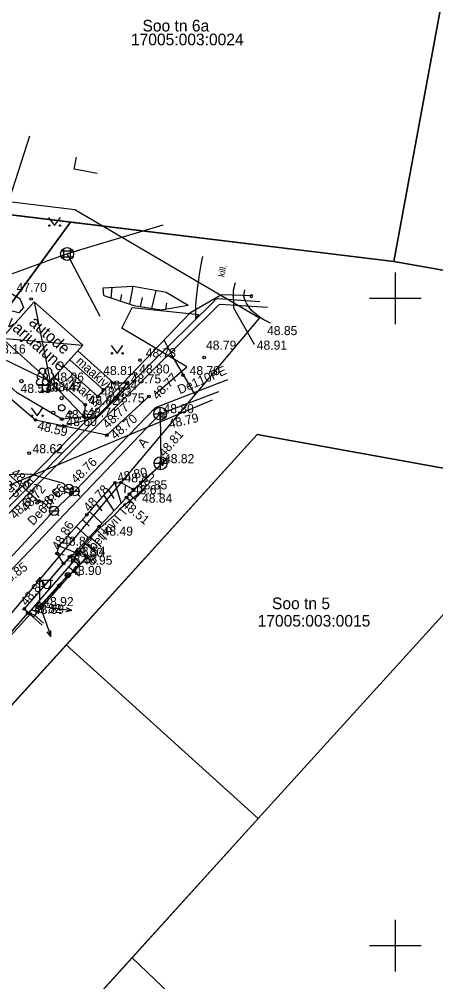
# Model space of a CAD drawing. Extents: x 640876 to 641418, y 6455595 to 6456085.
# Drawn here: x 641221 to 641253.1, y 6455847.2 to 6455921.6 of the extents above; entities that cross this region are included whole.
import ezdxf

# ---------------------------------------------------------------- set-up
doc = ezdxf.new("R2010")
doc.units = 0
for name, color, linetype in [('AED', 7, 'Continuous'), ('DKAEV', 7, 'Continuous'), ('DTRASS', 7, 'Continuous'), ('HALJASTUS', 7, 'Continuous'), ('HOONE', 7, 'Continuous'), ('HOONEDET', 7, 'Continuous'), ('KKAEV', 7, 'Continuous'), ('KORGUS', 7, 'Continuous'), ('KTRASS', 7, 'Continuous'), ('MOOTKORG', 7, 'Continuous'), ('MOOTMPUNKT', 7, 'Continuous'), ('MOOTPIIR', 7, 'Continuous'), ('MPOHULIIN', 7, 'Continuous'), ('PIIR', 7, 'Continuous'), ('POST', 7, 'Continuous'), ('PUU', 7, 'Continuous'), ('RELJEEF', 7, 'Continuous'), ('SITRASS', 7, 'Continuous'), ('TEE', 7, 'Continuous'), ('TTRASS', 7, 'Continuous'), ('VEEKOGU', 7, 'Continuous'), ('VKAEV', 7, 'Continuous'), ('VORK', 7, 'Continuous'), ('VTRASS', 7, 'Continuous')]:
    doc.layers.add(name, color=color, linetype=linetype)

msp = doc.modelspace()

# ---------------------------------------------------------------- linework, layer by layer
at = {"layer": 'AED'}
for points in [[(641221.756, 6455912.51), (641220.217, 6455907.717)], [(641221.825, 6455875.625), (641216.829, 6455870.111), (641212.099, 6455864.686)], [(641222.731, 6455874.755), (641221.819, 6455875.569)]]:
    msp.add_lwpolyline(points, dxfattribs=at)
at = {"layer": 'DKAEV'}
for p, q in [((641224.411, 6455902.987), (641224.411, 6455903.853)), ((641224.911, 6455903.853), (641224.911, 6455902.987)), ((641224.228, 6455903.67), (641225.094, 6455903.67)), ((641225.094, 6455903.17), (641224.228, 6455903.17))]:
    msp.add_line(p, q, dxfattribs=at)
msp.add_circle((641224.661, 6455903.42), 0.5, dxfattribs=at)
at = {"layer": 'DTRASS'}
for p, q in [((641232.042, 6455905.657), (641224.661, 6455903.42)), ((641224.661, 6455903.42), (641211.718, 6455898.734)), ((641225.567, 6455903.694), (641224.661, 6455903.42)), ((641227.214, 6455898.595), (641224.661, 6455903.42)), ((641220.013, 6455885.484), (641235.878, 6455892.151))]:
    msp.add_line(p, q, dxfattribs=at)
at = {"layer": 'HALJASTUS'}
for p, q in [((641223.235, 6455906.226), (641223.699, 6455905.619)), ((641223.699, 6455905.619), (641224.144, 6455906.226)), ((641228.057, 6455896.352), (641228.52, 6455895.745)), ((641228.52, 6455895.745), (641228.966, 6455896.352)), ((641221.883, 6455891.532), (641222.347, 6455890.925)), ((641222.347, 6455890.925), (641222.792, 6455891.532)), ((641221.71, 6455875.698), (641225.203, 6455879.729))]:
    msp.add_line(p, q, dxfattribs=at)
for points in [[(641225.967, 6455890.838), (641224.248, 6455890.658), (641220.812, 6455892.688), (641218.042, 6455895.173), (641218.862, 6455895.734), (641223.364, 6455893.565), (641225.967, 6455890.838)], [(641232.499, 6455887.68), (641229.484, 6455884.866), (641230.002, 6455884.376)], [(641229.917, 6455884.535), (641230.717, 6455885.322)], [(641221.355, 6455876.005), (641222.066, 6455875.392), (641225.559, 6455879.422), (641224.848, 6455880.035), (641221.355, 6455876.005)]]:
    msp.add_lwpolyline(points, dxfattribs=at)
for centre in [(641223.298, 6455905.619), (641224.126, 6455905.619), (641228.119, 6455895.745), (641228.948, 6455895.745), (641221.946, 6455890.925), (641222.775, 6455890.925)]:
    msp.add_circle(centre, 0.055, dxfattribs=at)
at = {"layer": 'HOONE'}
msp.add_lwpolyline([(641226.979, 6455909.64), (641225.211, 6455909.978), (641225.386, 6455910.893)], dxfattribs=at)
msp.add_lwpolyline([(641222.131, 6455899.722), (641219.619, 6455896.91), (641223.364, 6455893.565), (641225.876, 6455896.377)], close=True, dxfattribs=at)
at = {"layer": 'HOONEDET'}
for p, q in [((641222.131, 6455899.722), (641223.364, 6455893.565)), ((641219.619, 6455896.91), (641225.876, 6455896.377))]:
    msp.add_line(p, q, dxfattribs=at)
at = {"layer": 'KKAEV'}
for p, q in [((641231.848, 6455890.586), (641231.848, 6455891.586)), ((641231.348, 6455891.086), (641232.348, 6455891.086)), ((641231.88, 6455886.759), (641231.88, 6455887.759)), ((641231.38, 6455887.259), (641232.38, 6455887.259))]:
    msp.add_line(p, q, dxfattribs=at)
for centre in [(641231.848, 6455891.086), (641231.88, 6455887.259)]:
    msp.add_circle(centre, 0.5, dxfattribs=at)
at = {"layer": 'KORGUS'}
msp.add_line((641238.968, 6455900.207), (641238.905, 6455900.257), dxfattribs=at)
for centre in [(641221.885, 6455899.942), (641230.29, 6455895.22), (641235.25, 6455895.43), (641229.95, 6455894.17), (641233.609, 6455894.064), (641228.274, 6455893.451), (641230.967, 6455892.412), (641222.234, 6455890.597), (641226.877, 6455890.799), (641232.071, 6455890.846), (641227.727, 6455889.418), (641221.737, 6455888.032), (641231.997, 6455887.499), (641228.359, 6455885.741), (641224.942, 6455884.851), (641229.252, 6455884.61), (641222.347, 6455884.191), (641222.487, 6455884.336), (641222.525, 6455884.321), (641226.183, 6455883.28), (641227.141, 6455882.364), (641223.897, 6455880.282), (641225.559, 6455879.422), (641221.355, 6455876.005)]:
    msp.add_circle(centre, 0.1, dxfattribs=at)
msp.add_arc((641238.88, 6455900.16), 0.1, 75.27044, 28.34425, dxfattribs=at)
at = {"layer": 'KTRASS'}
for q in [(641232.097, 6455887.148), (641232.072, 6455887.115)]:
    msp.add_line((641231.88, 6455887.259), q, dxfattribs=at)
for points in [[(641231.848, 6455891.086), (641236.371, 6455892.804)], [(641216.001, 6455874.47), (641231.848, 6455891.086), (641231.899, 6455887.222)], [(641231.899, 6455887.222), (641232.051, 6455887.087)]]:
    msp.add_lwpolyline(points, dxfattribs=at)
at = {"layer": 'MOOTMPUNKT'}
for centre in [(641223.364, 6455893.565), (641229.32, 6455893.432), (641222.751, 6455892.791), (641223.215, 6455892.821), (641227.462, 6455892.937), (641227.031, 6455892.414), (641228.036, 6455891.957), (641226.069, 6455891.769), (641231.84, 6455891.123), (641224.248, 6455890.658), (641225.967, 6455890.838), (641224.354, 6455890.139), (641231.88, 6455887.259), (641228.828, 6455885.781), (641229.791, 6455885.236), (641229.484, 6455884.866), (641224.02, 6455880.889), (641224.848, 6455880.035), (641225.015, 6455880.11), (641224.378, 6455879.517), (641224.713, 6455878.622), (641222.563, 6455876.22), (641221.631, 6455875.683), (641221.825, 6455875.625)]:
    msp.add_circle(centre, 0.1, dxfattribs=at)
at = {"layer": 'MOOTPIIR'}
msp.add_lwpolyline([(641060.916, 6455895.936), (641100.061, 6455950.482), (641099.586, 6455952.159), (641069.132, 6455984.035), (641066.132, 6455988.623), (641076.463, 6456005.049), (641230.642, 6456010.048), (641237.36, 6455995.24), (641237.24, 6455992.81), (641236.258, 6455990.888), (641229.041, 6455971.315), (641203.026, 6455909.57), (641225.257, 6455906.847), (641239.512, 6455898.491), (641200.195, 6455851.697), (641192.016, 6455859.099), (641169.785, 6455829.138), (641192.025, 6455807.568), (641252.96, 6455758.075), (641231.388, 6455736.74), (641191.474, 6455775.975), (641152.419, 6455787.914), (641136.351, 6455788.307), (641049.066, 6455856.043)], dxfattribs=at)
at = {"layer": 'MPOHULIIN'}
for p, q in [((641222.735, 6455876.402), (641224.282, 6455878.035)), ((641224.282, 6455878.035), (641223.863, 6455877.811)), ((641224.282, 6455878.035), (641224.08, 6455877.605)), ((641222.563, 6455876.22), (641222.563, 6455876.22)), ((641222.563, 6455876.22), (641222.563, 6455876.22)), ((641222.563, 6455876.22), (641222.563, 6455876.22)), ((641222.648, 6455875.985), (641223.412, 6455873.869)), ((641222.811, 6455876.186), (641225.04, 6455875.878)), ((641225.04, 6455875.878), (641224.572, 6455875.793)), ((641225.04, 6455875.878), (641224.613, 6455876.089)), ((641223.412, 6455873.869), (641223.119, 6455874.243)), ((641223.412, 6455873.869), (641223.4, 6455874.344))]:
    msp.add_line(p, q, dxfattribs=at)
at = {"layer": 'PIIR'}
for points in [[(641222.58, 6455998.61), (641237.36, 6455995.24), (641235.34, 6455991.29), (641228.11, 6455971.68), (641220.5, 6455953.19), (641213.41, 6455936.25), (641201.58, 6455908.74), (641224.93, 6455905.88), (641191.87, 6455860.58), (641157.02, 6455885.66), (641160.91, 6455891.99), (641102.26, 6455951.82), (641074.95, 6455979.64), (641084.84, 6455991.92)], [(641270.69, 6455899.15), (641249.88, 6455902.84), (641253.51, 6455922.51), (641213.41, 6455936.25), (641220.5, 6455953.19), (641280.77, 6455915.37)], [(641201.58, 6455908.74), (641213.41, 6455936.25), (641253.51, 6455922.51), (641249.88, 6455902.84)], [(641239.33, 6455889.47), (641262.53, 6455885.29), (641239.42, 6455859.81), (641224.6, 6455873.24)], [(641270.46, 6455810.04), (641229.68, 6455849.06), (641239.42, 6455859.81), (641262.53, 6455885.29), (641292.55, 6455879.89), (641315.35, 6455858.84)], [(641224.6, 6455873.24), (641239.42, 6455859.81), (641199.12, 6455815.36), (641184.3, 6455828.79)], [(641250.06, 6455787.79), (641207.91, 6455825.07), (641229.68, 6455849.06), (641270.46, 6455810.04)]]:
    msp.add_lwpolyline(points, close=True, dxfattribs=at)
msp.add_lwpolyline([(641315.35, 6455858.84), (641292.55, 6455879.89), (641262.53, 6455885.29), (641239.33, 6455889.47), (641203.18, 6455849.61), (641191.84, 6455860.59), (641224.93, 6455905.88), (641249.88, 6455902.84), (641270.69, 6455899.15), (641280.77, 6455915.37), (641291.33, 6455932.26), (641301.94, 6455948.72)], dxfattribs=at)
at = {"layer": 'POST'}
for p, q in [((641224.713, 6455878.622), (641222.563, 6455876.22)), ((641222.563, 6455876.47), (641222.563, 6455878.47)), ((641222.563, 6455878.22), (641223.563, 6455878.22)), ((641222.79, 6455877.899), (641222.79, 6455878.22)), ((641223.402, 6455877.899), (641223.402, 6455878.22)), ((641222.563, 6455876.22), (641222.563, 6455876.22))]:
    msp.add_line(p, q, dxfattribs=at)
for centre, radius in [((641224.713, 6455878.622), 0.2), ((641222.563, 6455876.22), 0.25)]:
    msp.add_circle(centre, radius, dxfattribs=at)
msp.add_arc((641223.096, 6455877.899), 0.306, 180, 0, dxfattribs=at)
at = {"layer": 'PUU'}
for p, q in [((641222.991, 6455893.266), (641222.511, 6455893.266)), ((641222.751, 6455892.791), (641222.751, 6455893.266)), ((641223.131, 6455892.791), (641222.751, 6455892.791)), ((641223.455, 6455893.296), (641222.975, 6455893.296)), ((641223.215, 6455892.821), (641223.215, 6455893.296)), ((641223.595, 6455892.821), (641223.215, 6455892.821))]:
    msp.add_line(p, q, dxfattribs=at)
for centre, radius in [((641221.133, 6455893.601), 0.125), ((641224.244, 6455892.287), 0.125), ((641223.594, 6455891.162), 0.125), ((641224.244, 6455891.537), 0.25), ((641224.894, 6455891.162), 0.125)]:
    msp.add_circle(centre, radius, dxfattribs=at)
for centre, radius, start, end in [((641222.581, 6455893.964), 0.233, 109.02174, 253.14154), ((641222.751, 6455894.311), 0.277, 332.5799, 207.4201), ((641223.045, 6455893.994), 0.233, 109.02174, 253.14154), ((641223.215, 6455894.341), 0.277, 332.5799, 207.4201), ((641222.921, 6455893.964), 0.233, 286.85082, 70.98591), ((641223.385, 6455893.994), 0.233, 286.85082, 70.98591), ((641222.514, 6455893.503), 0.238, 90.0016, 269.3953), ((641222.978, 6455893.533), 0.238, 90.0016, 269.3953), ((641222.988, 6455893.503), 0.238, 270.6047, 89.9984), ((641223.452, 6455893.533), 0.238, 270.6047, 89.9984)]:
    msp.add_arc(centre, radius, start, end, dxfattribs=at)
at = {"layer": 'RELJEEF'}
for p, q in [((641228.359, 6455885.741), (641228.827, 6455884.158)), ((641229.154, 6455885.597), (641229.113, 6455884.977)), ((641227.508, 6455884.778), (641228.279, 6455883.575)), ((641227.87, 6455885.188), (641228.269, 6455884.539)), ((641226.917, 6455884.11), (641227.353, 6455883.58)), ((641226.395, 6455883.52), (641227.375, 6455882.613)), ((641225.362, 6455882.372), (641226.326, 6455881.5)), ((641225.841, 6455882.902), (641226.363, 6455882.406)), ((641224.691, 6455881.631), (641225.254, 6455881.327)), ((641224.02, 6455880.889), (641225.268, 6455880.379)), ((641223.897, 6455880.282), (641224.434, 6455880.173)), ((641224.378, 6455879.517), (641224.569, 6455879.637))]:
    msp.add_line(p, q, dxfattribs=at)
for points in [[(641227.45, 6455900.805), (641229.757, 6455900.944), (641232.312, 6455900.46), (641234.015, 6455899.477)], [(641228.074, 6455900.018), (641228.137, 6455900.856)], [(641229.498, 6455899.549), (641229.757, 6455900.944)], [(641227.496, 6455900.209), (641227.45, 6455900.805)], [(641227.496, 6455900.209), (641229.819, 6455899.443), (641231.916, 6455899.1), (641234.015, 6455899.477)], [(641228.78, 6455899.785), (641228.886, 6455900.301)], [(641231.215, 6455899.215), (641231.528, 6455900.608)], [(641230.336, 6455899.358), (641230.476, 6455900.063)], [(641232.288, 6455899.167), (641232.371, 6455899.617)], [(641224.378, 6455879.517), (641223.897, 6455880.282), (641224.02, 6455880.889), (641226.183, 6455883.28), (641228.359, 6455885.741), (641228.828, 6455885.781), (641229.791, 6455885.236)], [(641224.833, 6455879.235), (641225.63, 6455880.516)], [(641225.213, 6455878.909), (641226.173, 6455880.028)], [(641224.833, 6455879.235), (641225.612, 6455878.567)]]:
    msp.add_lwpolyline(points, dxfattribs=at)
at = {"layer": 'SITRASS'}
for points in [[(641239.002, 6455900.181), (641236.569, 6455900.278), (641234.143, 6455898.845), (641234.143, 6455898.845), (641228.363, 6455892.82)], [(641234.54, 6455892.576), (641232.986, 6455895.232), (641232.146, 6455896.763)], [(641160.717, 6455890.02), (641160.061, 6455889.202), (641160.124, 6455887.433), (641162.714, 6455885.215), (641168.31, 6455881.226), (641178.228, 6455873.851), (641188.611, 6455866.439), (641195.817, 6455861.122), (641198.143, 6455862.18), (641205.423, 6455869.555), (641212.959, 6455877.434), (641219.89, 6455884.166), (641222.806, 6455887.129), (641228.363, 6455892.82), (641230.103, 6455894.633)]]:
    msp.add_lwpolyline(points, dxfattribs=at)
at = {"layer": 'TEE'}
for p, q in [((641230.967, 6455892.412), (641227.727, 6455889.418)), ((641224.354, 6455890.139), (641226.877, 6455890.799))]:
    msp.add_line(p, q, dxfattribs=at)
for points in [[(641227.727, 6455889.418), (641222.234, 6455890.597), (641218.433, 6455893.816), (641212.015, 6455899.131), (641206.417, 6455903.827), (641200.844, 6455908.419), (641200.675, 6455911.228), (641199.697, 6455919.825), (641198.745, 6455928.944), (641198.434, 6455930.44)], [(641231.467, 6455892.598), (641233.908, 6455894.708), (641228.9, 6455897.703), (641229.694, 6455899.292), (641234.799, 6455898.749), (641234.613, 6455898.441), (641234.599, 6455898.766), (641234.6, 6455899.022), (641234.605, 6455899.396), (641234.63, 6455899.818), (641234.668, 6455900.204), (641234.731, 6455900.747), (641234.802, 6455901.236), (641234.895, 6455901.848), (641234.994, 6455902.444), (641235.09, 6455902.983), (641235.133, 6455903.224)], [(641239.847, 6455898.337), (641239.482, 6455898.571), (641238.906, 6455899.068), (641238.535, 6455899.576), (641238.414, 6455899.831), (641238.31, 6455900.17), (641238.393, 6455900.66)], [(641240.358, 6455898.079), (641239.847, 6455898.337)], [(641223.672, 6455893.91), (641226.069, 6455891.769), (641225.967, 6455890.838), (641226.877, 6455890.799), (641228.036, 6455891.957), (641229.32, 6455893.432), (641228.274, 6455893.451), (641225.486, 6455895.941)], [(641224.871, 6455895.252), (641227.462, 6455892.937), (641227.031, 6455892.414), (641224.419, 6455894.747)], [(641211.095, 6455892.017), (641212.994, 6455892.362), (641214.224, 6455891.319), (641218.504, 6455887.834), (641222.487, 6455884.336)], [(641232.563, 6455887.765), (641229.791, 6455885.236), (641229.252, 6455884.61), (641229.813, 6455884.127)], [(641231.08, 6455885.803), (641230.04, 6455884.8), (641228.76, 6455883.74), (641228.33, 6455883.25), (641226.98, 6455882.06), (641226.09, 6455881.06), (641225.63, 6455880.52)], [(641229.252, 6455884.61), (641227.141, 6455882.364), (641225.015, 6455880.11)], [(641228.762, 6455883.741), (641229.214, 6455883.334)], [(641228.817, 6455882.808), (641228.322, 6455883.253)], [(641227.295, 6455880.794), (641226.5, 6455881.51)], [(641226.98, 6455882.06), (641227.737, 6455881.379)], [(641226.09, 6455881.06), (641226.927, 6455880.307)], [(641225.662, 6455879.535), (641225.015, 6455880.11), (641224.378, 6455879.517), (641221.355, 6455876.005), (641221.631, 6455875.683)], [(641226.497, 6455879.739), (641225.63, 6455880.52)], [(641207.942, 6455860.242), (641211.935, 6455864.789), (641216.758, 6455870.138), (641221.631, 6455875.683)], [(641221.64, 6455875.681), (641222.095, 6455875.575), (641222.838, 6455874.897)]]:
    msp.add_lwpolyline(points, dxfattribs=at)
at = {"layer": 'TTRASS'}
for points in [[(641146.983, 6455877.597), (641147.637, 6455878.312), (641148.076, 6455878.791), (641148.587, 6455879.349), (641156.827, 6455888.351), (641157.502, 6455889.088), (641158.299, 6455888.492), (641167.659, 6455881.582), (641177.2, 6455874.303), (641186.795, 6455867.097), (641195.745, 6455860.541), (641196.509, 6455859.853), (641197.119, 6455860.535), (641205.5, 6455869.137), (641213.939, 6455877.707), (641222.42, 6455886.169), (641230.878, 6455894.702), (641235.947, 6455899.687), (641236.146, 6455899.925), (641236.328, 6455899.987), (641239.542, 6455899.756)], [(641240.141, 6455899.285), (641236.489, 6455899.529), (641236.348, 6455899.464), (641230.948, 6455894.114), (641222.434, 6455885.667), (641213.976, 6455877.157), (641205.539, 6455868.624), (641197.23, 6455859.957), (641196.541, 6455859.328), (641186.928, 6455866.582), (641177.306, 6455873.752), (641167.696, 6455880.94), (641158.359, 6455887.923), (641157.562, 6455888.52), (641156.887, 6455887.782), (641148.647, 6455878.781), (641148.136, 6455878.223), (641147.697, 6455877.743), (641147.022, 6455877.006)]]:
    msp.add_lwpolyline(points, dxfattribs=at)
at = {"layer": 'VEEKOGU'}
msp.add_lwpolyline([(641213.621, 6455904.332), (641221.017, 6455899.99), (641221.3, 6455899.294), (641220.94, 6455898.882), (641219.91, 6455899.14), (641212.68, 6455902.963), (641206.258, 6455906.539), (641205.72, 6455907.399), (641206.101, 6455907.958), (641207.461, 6455907.25), (641213.621, 6455904.332)], dxfattribs=at)
at = {"layer": 'VKAEV'}
for p, q in [((641224.443, 6455885.293), (641225.143, 6455885.293)), ((641224.546, 6455885.046), (641224.406, 6455884.906)), ((641225.007, 6455884.856), (641224.867, 6455884.716)), ((641224.904, 6455885.103), (641225.604, 6455885.103)), ((641225.04, 6455885.046), (641225.18, 6455884.906)), ((641225.501, 6455884.856), (641225.641, 6455884.716)), ((641223.397, 6455883.335), (641223.257, 6455883.195)), ((641223.294, 6455883.582), (641223.994, 6455883.582)), ((641223.891, 6455883.335), (641224.031, 6455883.195))]:
    msp.add_line(p, q, dxfattribs=at)
for centre in [(641224.793, 6455885.293), (641225.254, 6455885.103), (641223.644, 6455883.582)]:
    msp.add_circle(centre, 0.35, dxfattribs=at)
at = {"layer": 'VORK'}
for p, q in [((641250, 6455902), (641250, 6455898)), ((641248, 6455900), (641252, 6455900)), ((641250, 6455852), (641250, 6455848)), ((641248, 6455850), (641252, 6455850))]:
    msp.add_line(p, q, dxfattribs=at)
at = {"layer": 'VTRASS'}
for points in [[(641239.121, 6455896.442), (641237.53, 6455899.228), (641237.51, 6455900.617), (641237.673, 6455901.226)], [(641224.984, 6455884.848), (641225.125, 6455884.961), (641225.254, 6455885.103), (641231.482, 6455891.574), (641237.063, 6455893.719)], [(641225.125, 6455884.961), (641224.793, 6455885.293), (641224.379, 6455885.681), (641221.849, 6455886.408), (641219.207, 6455886.366), (641215.232, 6455884.875), (641209.997, 6455882.32), (641208.525, 6455881.71), (641207.703, 6455882.321), (641203.623, 6455885.661)], [(641213.817, 6455872.768), (641215.778, 6455875.106), (641223.644, 6455883.582), (641224.984, 6455884.848)]]:
    msp.add_lwpolyline(points, dxfattribs=at)

# ---------------------------------------------------------------- texts
at = {"layer": 'HOONE'}
for s, p in [('varjualune', (641219.927, 6455897.986)), ('autode', (641221.646, 6455898.033))]:
    msp.add_text(s, height=0.9, rotation=318.66345, dxfattribs=at).set_placement(p)
at = {"layer": 'KORGUS'}
for s, p in [(' 47.70', (641220.502, 6455900.492)), ('48.85', (641240.096, 6455897.153)), ('48.79', (641235.385, 6455896.029)), ('48.91', (641239.304, 6455896.029)), ('48.73', (641230.73, 6455895.443)), ('48.80', (641230.226, 6455894.19)), (' 48.81', (641227.191, 6455894.069)), ('48.70', (641234.119, 6455894.062)), (' 48.62', (641221.737, 6455888.032)), (' 48.49', (641227.141, 6455881.664)), (' 48.95', (641225.559, 6455879.422))]:
    msp.add_text(s, height=0.7, dxfattribs=at).set_placement(p)
for s, rotation, p in [(' 48.77', 46.33283, (641231.473, 6455891.929)), (' 48.77', 42.89985, (641227.597, 6455889.704)), (' 48.59', 346.58616, (641222.072, 6455889.916)), (' 48.70', 40.79022, (641228.184, 6455888.888)), (' 48.79', 12.92553, (641232.336, 6455889.879)), (' 48.81', 49.12266, (641231.997, 6455887.499)), (' 48.76', 44.59846, (641225.183, 6455885.461)), ('48.51', 320.94614, (641220.282, 6455886.398)), (' 48.80', 11.83099, (641228.359, 6455885.741)), ('48.55', 315.83598, (641219.06, 6455886.17)), (' 48.72', 50.28505, (641221.383, 6455883.237)), ('48.66', 44.80756, (641222.938, 6455883.609)), (' 48.78', 47.29941, (641226.183, 6455883.28)), ('48.68', 44.23146, (641220.662, 6455882.896)), (' 48.51', 320.26335, (641228.656, 6455884.133)), (' 48.86', 59.3362, (641223.897, 6455880.282)), (' 48.85', 36.8232, (641219.599, 6455877.542)), (' 48.85', 49.76189, (641221.355, 6455876.005))]:
    msp.add_text(s, height=0.7, rotation=rotation, dxfattribs=at).set_placement(p)
at = {"layer": 'MOOTKORG'}
for s, p in [(' 48.16', (641218.862, 6455895.734)), (' 48.96', (641223.364, 6455893.565)), (' 48.44', (641222.751, 6455892.791)), (' 48.47', (641223.215, 6455892.821)), (' 48.84', (641227.462, 6455892.937)), (' 48.75', (641229.32, 6455893.432)), (' 48.53', (641220.812, 6455892.688)), (' 48.83', (641227.031, 6455892.414)), (' 48.75', (641228.036, 6455891.957)), (' 48.82', (641226.069, 6455891.769)), (' 48.63', (641224.248, 6455890.658)), (' 48.71', (641225.967, 6455890.838)), (' 48.80', (641231.84, 6455891.123)), (' 48.60', (641224.354, 6455890.139)), (' 48.82', (641231.88, 6455887.259)), (' 48.82', (641228.828, 6455885.781)), (' 48.70', (641219.157, 6455885.197)), (' 48.61', (641229.484, 6455884.866)), (' 48.85', (641229.791, 6455885.236)), (' 48.84', (641230.181, 6455884.207)), (' 48.82', (641224.02, 6455880.889)), (' 48.54', (641225.015, 6455880.11)), (' 48.88', (641224.378, 6455879.517)), (' 48.60', (641224.848, 6455880.035)), (' 48.90', (641224.713, 6455878.622)), (' 48.82', (641221.631, 6455875.683)), (' 48.89', (641221.825, 6455875.625)), (' 48.92', (641222.563, 6455876.22))]:
    msp.add_text(s, height=0.7, dxfattribs=at).set_placement(p)
at = {"layer": 'PIIR'}
for s, p in [('Soo tn 6a', (641230.481, 6455920.605)), ('17005:003:0024', (641229.59, 6455919.54)), ('Soo tn 5', (641240.479, 6455875.987)), ('17005:003:0015', (641239.37, 6455874.64))]:
    msp.add_text(s, height=0.9, dxfattribs=at).set_placement(p)
at = {"layer": 'TEE'}
for s, height, rotation, p in [('kill.', 0.5, 78.28469, (641236.792, 6455901.605)), ('maakivi', 0.7, 318.02897, (641225.295, 6455895.052)), ('maakivi', 0.7, 318.02897, (641224.513, 6455893.674)), ('A', 0.7, 51.16433, (641230.593, 6455888.388)), ('bet kivi', 0.7, 49.40003, (641226.775, 6455880.467))]:
    msp.add_text(s, height=height, rotation=rotation, dxfattribs=at).set_placement(p)
at = {"layer": 'VTRASS'}
for s, rotation, p in [('De110PE', 23.54202, (641233.37, 6455892.58)), ('De63PE', 47.31463, (641222.04, 6455882.41))]:
    msp.add_text(s, height=0.7, rotation=rotation, dxfattribs=at).set_placement(p)

doc.saveas('drawing.dxf')
